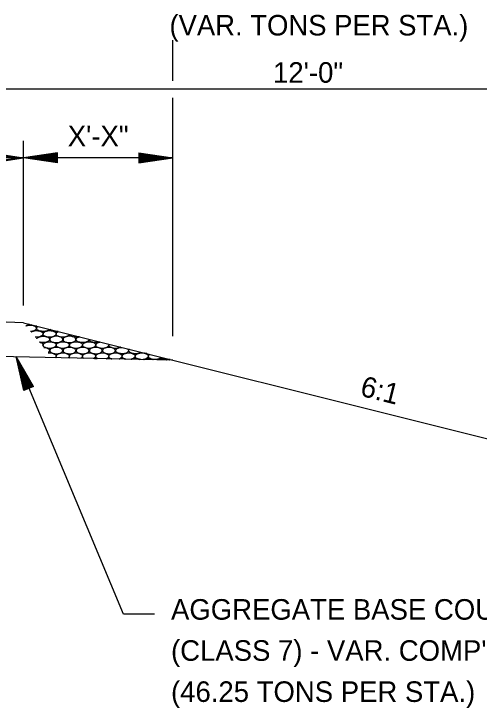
# Model space of a CAD drawing. Extents: x 138 to 3619, y -519 to 1449.
# Drawn here: x 755.2 to 890.9, y -441.4 to -238.8 of the extents above; entities that cross this region are included whole.
import ezdxf

# ---------------------------------------------------------------- set-up
doc = ezdxf.new("R2010")
doc.units = 0
doc.layers.add('R_Annotation', color=7, linetype='Continuous')
doc.layers.add('R_Dimension', color=7, linetype='Continuous')

msp = doc.modelspace()

# ---------------------------------------------------------------- linework, layer by layer
at = {"layer": 'R_Annotation'}
for p, q in [((758, -328.91), (718, -327.31)), ((758, -328.91), (958, -378.91)), ((801.63, -339.82), (688, -337.55))]:
    msp.add_line(p, q, dxfattribs=at)
at = {"layer": 'R_Dimension'}
for p, q in [((801.63, -258.28), (801.63, -246.46)), ((958, -260.78), (718, -260.78)), ((801.63, -332.86), (801.63, -263.28)), ((758, -323.91), (758, -275.78)), ((801.63, -332.86), (801.63, -275.78)), ((748, -279.28), (758, -280.78)), ((748, -279.53), (756.33, -280.78)), ((768, -279.28), (758, -280.78)), ((768, -279.53), (759.67, -280.78)), ((768, -282.28), (768, -279.28)), ((791.63, -279.28), (801.63, -280.78)), ((791.63, -279.28), (791.63, -282.28)), ((791.63, -279.53), (799.96, -280.78)), ((801.63, -280.78), (414.37, -280.78)), ((748, -282.28), (758, -280.78)), ((748, -282.03), (756.33, -280.78)), ((768, -282.28), (758, -280.78)), ((768, -282.03), (759.67, -280.78)), ((768, -279.79), (761.39, -280.78)), ((768, -281.78), (761.39, -280.78)), ((768, -280.04), (763.06, -280.78)), ((768, -281.53), (763.06, -280.78)), ((768, -280.29), (764.75, -280.78)), ((768, -281.27), (764.75, -280.78)), ((768, -280.55), (766.42, -280.78)), ((768, -281.02), (766.42, -280.78)), ((791.63, -279.79), (798.24, -280.78)), ((791.63, -280.04), (796.58, -280.78)), ((791.63, -280.3), (794.88, -280.78)), ((791.63, -280.55), (793.21, -280.78)), ((791.63, -282.28), (801.63, -280.78)), ((791.63, -281.27), (794.88, -280.78)), ((791.63, -281.78), (798.24, -280.78)), ((791.63, -282.03), (799.96, -280.78)), ((791.63, -281.53), (796.58, -280.78)), ((791.63, -281.02), (793.21, -280.78)), ((760.93, -347.56), (755.86, -338.81)), ((758.14, -348.66), (755.86, -338.81)), ((760.69, -347.65), (756.47, -340.36)), ((758.37, -348.57), (756.47, -340.36)), ((758.61, -348.48), (757.1, -341.96)), ((760.46, -347.75), (757.1, -341.96)), ((760.22, -347.84), (757.71, -343.51)), ((758.84, -348.39), (757.71, -343.51)), ((759.08, -348.29), (758.34, -345.09)), ((759.98, -347.93), (758.34, -345.09)), ((760.93, -347.56), (758.14, -348.66)), ((759.31, -348.2), (758.95, -346.64)), ((759.75, -348.03), (758.95, -346.64))]:
    msp.add_line(p, q, dxfattribs=at)
msp.add_lwpolyline([(796.21, -413.96), (787.22, -413.96), (755.91, -338.91)], dxfattribs=at)
for points in [[(759.65, -329.33), (759.64, -329.34), (759.56, -329.43), (759.33, -329.59), (759.03, -329.72), (758.8, -329.79), (758.74, -329.81)], [(758.74, -329.81), (758.75, -329.8), (758.91, -329.75), (759.16, -329.67), (759.54, -329.59), (759.78, -329.58), (759.92, -329.59)], [(759.92, -329.59), (760.14, -329.59), (760.65, -329.65), (761.1, -329.8), (761.51, -330.02), (761.63, -330.14), (761.78, -330.38), (761.81, -330.6), (761.7, -330.81), (761.52, -331.02), (761.29, -331.16), (760.85, -331.35), (760.42, -331.46), (760.16, -331.47), (760.11, -331.47)], [(761.84, -329.89), (761.82, -329.89), (761.63, -329.89), (761.27, -329.86), (760.79, -329.72), (760.48, -329.62), (760.28, -329.53), (760.22, -329.5), (760.16, -329.45)], [(761.91, -329.89), (761.89, -329.89), (761.86, -329.89), (761.84, -329.89)], [(765.53, -330.8), (765.5, -330.85), (765.4, -330.99), (765.13, -331.16), (764.69, -331.35), (764.2, -331.47), (763.7, -331.46), (763.25, -331.42), (762.9, -331.37), (762.58, -331.29), (762.28, -331.12), (762.05, -330.95), (761.89, -330.71), (761.87, -330.5), (761.92, -330.29), (762.08, -330.08), (762.15, -330.02), (762.24, -329.97)], [(760.25, -331.64), (760.29, -331.6), (760.44, -331.53), (760.73, -331.4), (761.08, -331.29), (761.46, -331.21), (761.7, -331.2), (761.84, -331.21)], [(761.84, -331.21), (761.86, -331.21), (761.87, -331.21), (761.89, -331.21)], [(763.67, -332.17), (763.67, -332.18), (763.67, -332.35), (763.57, -332.5), (763.39, -332.69), (763.17, -332.84), (762.72, -333.03), (762.35, -333.13), (762.03, -333.15), (761.94, -333.15), (761.84, -333.14)], [(761.89, -331.21), (762.11, -331.21), (762.61, -331.27), (763.06, -331.42), (763.48, -331.64), (763.61, -331.76), (763.74, -332), (763.75, -332.08), (763.76, -332.16), (763.76, -332.16), (763.76, -332.17)], [(765.68, -333.14), (765.66, -333.14), (765.47, -333.15), (765.11, -333.12), (764.63, -332.98), (764.32, -332.87), (764.02, -332.75), (763.89, -332.63), (763.76, -332.39), (763.75, -332.29), (763.75, -332.18), (763.75, -332.17)], [(763.81, -332.17), (763.81, -332.16), (763.81, -332.03), (763.84, -331.91), (764.01, -331.68), (764.21, -331.56), (764.57, -331.4), (764.92, -331.29), (765.3, -331.21), (765.54, -331.2), (765.68, -331.21)], [(765.68, -331.21), (765.7, -331.21), (765.71, -331.21), (765.73, -331.21)], [(767.51, -332.17), (767.51, -332.18), (767.51, -332.35), (767.41, -332.5), (767.23, -332.69), (767.01, -332.84), (766.56, -333.03), (766.19, -333.13), (765.87, -333.15), (765.78, -333.15), (765.68, -333.14)], [(765.73, -331.21), (765.95, -331.21), (766.45, -331.27), (766.9, -331.42), (767.32, -331.64), (767.45, -331.76), (767.58, -332), (767.59, -332.08), (767.6, -332.16), (767.6, -332.16), (767.6, -332.17)], [(768.12, -331.44), (768.06, -331.45), (767.88, -331.47), (767.54, -331.46), (767.09, -331.42), (766.74, -331.37), (766.42, -331.29), (766.15, -331.14), (765.94, -330.98), (765.85, -330.88)], [(769.52, -333.14), (769.5, -333.14), (769.31, -333.15), (768.95, -333.12), (768.47, -332.98), (768.16, -332.87), (767.86, -332.75), (767.73, -332.63), (767.6, -332.39), (767.59, -332.29), (767.59, -332.18), (767.59, -332.17)], [(767.65, -332.17), (767.65, -332.16), (767.65, -332.03), (767.68, -331.91), (767.85, -331.68), (768.01, -331.58), (768.18, -331.5), (768.23, -331.47)], [(771.35, -332.25), (771.33, -332.39), (771.18, -332.62), (770.85, -332.84), (770.4, -333.03), (770.03, -333.13), (769.71, -333.15), (769.62, -333.15), (769.52, -333.14)], [(761.84, -333.14), (761.82, -333.14), (761.7, -333.14), (761.58, -333.14), (761.48, -333.13)], [(761.91, -333.64), (761.92, -333.57), (762.04, -333.35), (762.29, -333.19), (762.65, -333.03), (763, -332.93), (763.38, -332.84), (763.62, -332.83), (763.76, -332.84)], [(763.76, -332.84), (763.98, -332.84), (764.49, -332.91), (764.94, -333.05), (765.35, -333.28), (765.47, -333.4), (765.62, -333.63), (765.65, -333.86), (765.54, -334.07), (765.36, -334.27), (765.13, -334.42), (764.69, -334.61), (764.2, -334.72), (763.7, -334.72), (763.25, -334.68), (762.9, -334.62), (762.71, -334.58), (762.69, -334.57), (762.67, -334.57)], [(767.6, -332.84), (767.82, -332.84), (768.33, -332.91), (768.78, -333.05), (769.19, -333.28), (769.31, -333.4), (769.46, -333.63), (769.49, -333.86), (769.38, -334.07), (769.2, -334.27), (768.97, -334.42), (768.53, -334.61), (768.04, -334.72), (767.54, -334.72), (767.09, -334.68), (766.74, -334.62), (766.42, -334.55), (766.12, -334.38), (765.89, -334.2), (765.73, -333.96), (765.71, -333.75), (765.76, -333.54), (765.93, -333.31), (766.13, -333.19), (766.49, -333.03), (766.84, -332.93), (767.22, -332.84), (767.46, -332.83), (767.6, -332.84)], [(771.44, -332.84), (771.66, -332.84), (772.17, -332.91), (772.62, -333.05), (773.03, -333.28), (773.15, -333.4), (773.3, -333.63), (773.33, -333.86), (773.22, -334.07), (773.04, -334.27), (772.81, -334.42), (772.37, -334.61), (771.88, -334.72), (771.38, -334.72), (770.93, -334.68), (770.58, -334.62), (770.26, -334.55), (769.96, -334.38), (769.73, -334.2), (769.57, -333.96), (769.55, -333.75), (769.6, -333.54), (769.77, -333.31), (769.97, -333.19), (770.33, -333.03), (770.68, -332.93), (771.06, -332.84), (771.3, -332.83), (771.44, -332.84)], [(773.36, -333.14), (773.34, -333.14), (773.15, -333.15), (772.79, -333.12), (772.31, -332.98), (772, -332.87), (771.7, -332.75), (771.57, -332.63), (771.45, -332.4), (771.43, -332.34), (771.43, -332.27)], [(774.33, -333), (774.32, -333), (774.09, -333.07), (773.77, -333.15), (773.46, -333.15), (773.36, -333.14)], [(777.15, -333.7), (777.16, -333.73), (777.14, -333.9), (777.06, -334.07), (776.88, -334.27), (776.65, -334.42), (776.21, -334.61), (775.72, -334.72), (775.22, -334.72), (774.77, -334.68), (774.42, -334.62), (774.1, -334.55), (773.8, -334.38), (773.57, -334.2), (773.41, -333.96), (773.39, -333.75), (773.44, -333.54), (773.61, -333.31), (773.81, -333.19), (774.08, -333.07), (774.25, -333.01), (774.32, -332.99)], [(780.33, -334.49), (780.25, -334.53), (779.96, -334.63), (779.56, -334.72), (779.06, -334.72), (778.61, -334.68), (778.26, -334.62), (777.94, -334.55), (777.64, -334.38), (777.41, -334.2), (777.25, -333.96), (777.24, -333.85), (777.25, -333.75), (777.25, -333.73)], [(762.67, -334.57), (762.89, -334.62), (763.1, -334.7), (763.48, -334.9), (763.61, -335.01), (763.74, -335.26), (763.75, -335.33), (763.76, -335.41), (763.76, -335.42), (763.76, -335.42)], [(763.67, -335.42), (763.67, -335.44), (763.67, -335.53), (763.64, -335.62), (763.6, -335.69)], [(765.68, -336.4), (765.66, -336.4), (765.47, -336.4), (765.11, -336.37), (764.63, -336.23), (764.32, -336.13), (764.02, -336), (763.89, -335.89), (763.76, -335.64), (763.75, -335.54), (763.75, -335.44), (763.75, -335.42)], [(763.81, -335.42), (763.81, -335.42), (763.81, -335.29), (763.84, -335.16), (764.01, -334.93), (764.21, -334.81), (764.57, -334.65), (764.92, -334.55), (765.3, -334.46), (765.54, -334.45), (765.68, -334.46)], [(763.94, -336.1), (764.1, -336.11), (764.54, -336.18), (764.94, -336.31), (765.35, -336.53), (765.47, -336.65), (765.62, -336.89), (765.65, -337.11), (765.54, -337.32), (765.36, -337.53), (765.29, -337.58), (765.2, -337.63), (765.2, -337.63)], [(765.68, -334.46), (765.7, -334.46), (765.71, -334.46), (765.73, -334.46)], [(767.51, -335.42), (767.51, -335.44), (767.51, -335.61), (767.41, -335.75), (767.23, -335.95), (767.01, -336.1), (766.56, -336.28), (766.19, -336.39), (765.87, -336.4), (765.78, -336.4), (765.68, -336.4)], [(767.6, -336.1), (767.82, -336.1), (768.33, -336.16), (768.78, -336.31), (769.19, -336.53), (769.31, -336.65), (769.46, -336.89), (769.49, -337.11), (769.38, -337.32), (769.2, -337.53), (768.97, -337.67), (768.53, -337.86), (768.04, -337.98), (767.54, -337.97), (767.09, -337.93), (766.74, -337.88), (766.42, -337.8), (766.12, -337.63), (765.89, -337.46), (765.73, -337.22), (765.71, -337.01), (765.76, -336.8), (765.93, -336.57), (766.13, -336.45), (766.49, -336.29), (766.84, -336.18), (767.22, -336.1), (767.46, -336.09), (767.6, -336.1)], [(765.73, -334.46), (765.95, -334.46), (766.45, -334.53), (766.9, -334.67), (767.32, -334.9), (767.45, -335.01), (767.58, -335.26), (767.59, -335.33), (767.6, -335.41), (767.6, -335.42), (767.6, -335.42)], [(769.52, -336.4), (769.5, -336.4), (769.31, -336.4), (768.95, -336.37), (768.47, -336.23), (768.16, -336.13), (767.86, -336), (767.73, -335.89), (767.6, -335.64), (767.59, -335.54), (767.59, -335.44), (767.59, -335.42)], [(767.65, -335.42), (767.65, -335.42), (767.65, -335.29), (767.68, -335.16), (767.85, -334.93), (768.05, -334.81), (768.41, -334.65), (768.76, -334.55), (769.14, -334.46), (769.38, -334.45), (769.52, -334.46)], [(769.52, -334.46), (769.54, -334.46), (769.55, -334.46), (769.57, -334.46)], [(771.35, -335.42), (771.35, -335.44), (771.35, -335.61), (771.25, -335.75), (771.07, -335.95), (770.85, -336.1), (770.4, -336.28), (770.03, -336.39), (769.71, -336.4), (769.62, -336.4), (769.52, -336.4)], [(771.44, -336.1), (771.66, -336.1), (772.17, -336.16), (772.62, -336.31), (773.03, -336.53), (773.15, -336.65), (773.3, -336.89), (773.33, -337.11), (773.22, -337.32), (773.04, -337.53), (772.81, -337.67), (772.37, -337.86), (771.88, -337.98), (771.38, -337.97), (770.93, -337.93), (770.58, -337.88), (770.26, -337.8), (769.96, -337.63), (769.73, -337.46), (769.57, -337.22), (769.55, -337.01), (769.6, -336.8), (769.77, -336.57), (769.97, -336.45), (770.33, -336.29), (770.68, -336.18), (771.06, -336.1), (771.3, -336.09), (771.44, -336.1)], [(769.57, -334.46), (769.79, -334.46), (770.29, -334.53), (770.74, -334.67), (771.16, -334.9), (771.29, -335.01), (771.42, -335.26), (771.43, -335.33), (771.44, -335.41), (771.44, -335.42), (771.44, -335.42)], [(773.36, -336.4), (773.34, -336.4), (773.15, -336.4), (772.79, -336.37), (772.31, -336.23), (772, -336.13), (771.7, -336), (771.57, -335.89), (771.44, -335.64), (771.43, -335.54), (771.43, -335.44), (771.43, -335.42)], [(771.49, -335.42), (771.49, -335.42), (771.49, -335.29), (771.52, -335.16), (771.69, -334.93), (771.89, -334.81), (772.25, -334.65), (772.6, -334.55), (772.98, -334.46), (773.22, -334.45), (773.36, -334.46)], [(773.36, -334.46), (773.38, -334.46), (773.39, -334.46), (773.41, -334.46)], [(775.19, -335.42), (775.19, -335.44), (775.19, -335.61), (775.09, -335.75), (774.91, -335.95), (774.69, -336.1), (774.24, -336.28), (773.87, -336.39), (773.55, -336.4), (773.46, -336.4), (773.36, -336.4)], [(775.28, -336.1), (775.5, -336.1), (776.01, -336.16), (776.46, -336.31), (776.87, -336.53), (776.99, -336.65), (777.14, -336.89), (777.17, -337.11), (777.06, -337.32), (776.88, -337.53), (776.65, -337.67), (776.21, -337.86), (775.72, -337.98), (775.22, -337.97), (774.77, -337.93), (774.42, -337.88), (774.1, -337.8), (773.8, -337.63), (773.57, -337.46), (773.41, -337.22), (773.39, -337.01), (773.44, -336.8), (773.61, -336.57), (773.81, -336.45), (774.17, -336.29), (774.52, -336.18), (774.9, -336.1), (775.14, -336.09), (775.28, -336.1)], [(773.41, -334.46), (773.63, -334.46), (774.13, -334.53), (774.58, -334.67), (775, -334.9), (775.13, -335.01), (775.26, -335.26), (775.27, -335.33), (775.28, -335.41), (775.28, -335.42), (775.28, -335.42)], [(777.2, -336.4), (777.18, -336.4), (776.99, -336.4), (776.63, -336.37), (776.15, -336.23), (775.84, -336.13), (775.54, -336), (775.41, -335.89), (775.28, -335.64), (775.27, -335.54), (775.27, -335.44), (775.27, -335.42)], [(775.33, -335.42), (775.33, -335.42), (775.33, -335.29), (775.36, -335.16), (775.53, -334.93), (775.73, -334.81), (776.09, -334.65), (776.44, -334.55), (776.82, -334.46), (777.06, -334.45), (777.2, -334.46)], [(777.2, -334.46), (777.22, -334.46), (777.23, -334.46), (777.25, -334.46)], [(779.03, -335.42), (779.03, -335.44), (779.03, -335.61), (778.93, -335.75), (778.75, -335.95), (778.53, -336.1), (778.08, -336.28), (777.71, -336.39), (777.39, -336.4), (777.3, -336.4), (777.2, -336.4)], [(779.12, -336.1), (779.34, -336.1), (779.85, -336.16), (780.3, -336.31), (780.71, -336.53), (780.83, -336.65), (780.98, -336.89), (781.01, -337.11), (780.9, -337.32), (780.72, -337.53), (780.49, -337.67), (780.05, -337.86), (779.56, -337.98), (779.06, -337.97), (778.61, -337.93), (778.26, -337.88), (777.94, -337.8), (777.64, -337.63), (777.41, -337.46), (777.25, -337.22), (777.23, -337.01), (777.28, -336.8), (777.45, -336.57), (777.65, -336.45), (778.01, -336.29), (778.36, -336.18), (778.74, -336.1), (778.98, -336.09), (779.12, -336.1)], [(777.25, -334.46), (777.47, -334.46), (777.97, -334.53), (778.42, -334.67), (778.84, -334.9), (778.97, -335.01), (779.1, -335.26), (779.11, -335.33), (779.12, -335.41), (779.12, -335.42), (779.12, -335.42)], [(781.04, -336.4), (781.02, -336.4), (780.83, -336.4), (780.47, -336.37), (779.99, -336.23), (779.68, -336.13), (779.38, -336), (779.25, -335.89), (779.12, -335.64), (779.11, -335.54), (779.11, -335.44), (779.11, -335.42)], [(779.17, -335.42), (779.17, -335.42), (779.17, -335.29), (779.2, -335.16), (779.37, -334.93), (779.57, -334.81), (779.93, -334.65), (780.21, -334.57), (780.39, -334.52), (780.42, -334.52)], [(782.87, -335.42), (782.87, -335.44), (782.87, -335.61), (782.77, -335.75), (782.59, -335.95), (782.37, -336.1), (781.92, -336.28), (781.55, -336.39), (781.23, -336.4), (781.14, -336.4), (781.04, -336.4)], [(782.96, -336.1), (783.18, -336.1), (783.69, -336.16), (784.14, -336.31), (784.55, -336.53), (784.67, -336.65), (784.82, -336.89), (784.85, -337.11), (784.74, -337.32), (784.56, -337.53), (784.33, -337.67), (783.89, -337.86), (783.4, -337.98), (782.9, -337.97), (782.45, -337.93), (782.1, -337.88), (781.78, -337.8), (781.48, -337.63), (781.25, -337.46), (781.09, -337.22), (781.07, -337.01), (781.12, -336.8), (781.29, -336.57), (781.49, -336.45), (781.85, -336.29), (782.2, -336.18), (782.58, -336.1), (782.82, -336.09), (782.96, -336.1)], [(782.87, -335.13), (782.88, -335.15), (782.94, -335.24), (782.95, -335.33), (782.96, -335.41), (782.96, -335.42), (782.96, -335.42)], [(784.88, -336.4), (784.86, -336.4), (784.67, -336.4), (784.31, -336.37), (783.83, -336.23), (783.52, -336.13), (783.22, -336), (783.09, -335.89), (782.96, -335.64), (782.95, -335.54), (782.95, -335.44), (782.95, -335.42)], [(783.01, -335.42), (783.01, -335.42), (783.01, -335.33), (783.02, -335.25), (783.05, -335.18)], [(786.36, -336), (786.33, -336.02), (786.15, -336.13), (785.76, -336.28), (785.39, -336.39), (785.07, -336.4), (784.98, -336.4), (784.88, -336.4)], [(788.3, -336.49), (788.43, -336.57), (788.52, -336.68), (788.66, -336.89), (788.69, -337.11), (788.58, -337.32), (788.4, -337.53), (788.17, -337.67), (787.73, -337.86), (787.24, -337.98), (786.74, -337.97), (786.29, -337.93), (785.94, -337.88), (785.62, -337.8), (785.32, -337.63), (785.09, -337.46), (784.93, -337.22), (784.91, -337.01), (784.96, -336.8), (785.13, -336.57), (785.33, -336.45), (785.69, -336.29), (786.04, -336.18), (786.4, -336.1), (786.61, -336.09), (786.72, -336.09)], [(765.28, -337.73), (765.41, -337.71), (765.55, -337.71), (765.68, -337.72)], [(765.68, -337.72), (765.7, -337.72), (765.71, -337.72), (765.73, -337.72)], [(765.73, -337.72), (765.95, -337.72), (766.45, -337.78), (766.9, -337.93), (767.32, -338.15), (767.45, -338.27), (767.58, -338.51), (767.59, -338.59), (767.6, -338.67), (767.6, -338.67), (767.6, -338.68)], [(767.65, -338.68), (767.65, -338.67), (767.65, -338.54), (767.68, -338.42), (767.85, -338.19), (768.05, -338.07), (768.41, -337.91), (768.76, -337.8), (769.14, -337.72), (769.38, -337.71), (769.52, -337.72)], [(769.52, -337.72), (769.54, -337.72), (769.55, -337.72), (769.57, -337.72)], [(769.57, -337.72), (769.79, -337.72), (770.29, -337.78), (770.74, -337.93), (771.16, -338.15), (771.29, -338.27), (771.42, -338.51), (771.43, -338.59), (771.44, -338.67), (771.44, -338.67), (771.44, -338.68)], [(771.49, -338.68), (771.49, -338.67), (771.49, -338.54), (771.52, -338.42), (771.69, -338.19), (771.89, -338.07), (772.25, -337.91), (772.6, -337.8), (772.98, -337.72), (773.22, -337.71), (773.36, -337.72)], [(773.36, -337.72), (773.38, -337.72), (773.39, -337.72), (773.41, -337.72)], [(773.41, -337.72), (773.63, -337.72), (774.13, -337.78), (774.58, -337.93), (775, -338.15), (775.13, -338.27), (775.26, -338.51), (775.27, -338.59), (775.28, -338.67), (775.28, -338.67), (775.28, -338.68)], [(775.33, -338.68), (775.33, -338.67), (775.33, -338.54), (775.36, -338.42), (775.53, -338.19), (775.73, -338.07), (776.09, -337.91), (776.44, -337.8), (776.82, -337.72), (777.06, -337.71), (777.2, -337.72)], [(777.2, -337.72), (777.22, -337.72), (777.23, -337.72), (777.25, -337.72)], [(777.25, -337.72), (777.47, -337.72), (777.97, -337.78), (778.42, -337.93), (778.84, -338.15), (778.97, -338.27), (779.1, -338.51), (779.11, -338.59), (779.12, -338.67), (779.12, -338.67), (779.12, -338.68)], [(779.17, -338.68), (779.17, -338.67), (779.17, -338.54), (779.2, -338.42), (779.37, -338.19), (779.57, -338.07), (779.93, -337.91), (780.28, -337.8), (780.66, -337.72), (780.9, -337.71), (781.04, -337.72)], [(781.04, -337.72), (781.06, -337.72), (781.07, -337.72), (781.09, -337.72)], [(781.09, -337.72), (781.31, -337.72), (781.81, -337.78), (782.26, -337.93), (782.68, -338.15), (782.81, -338.27), (782.94, -338.51), (782.95, -338.59), (782.96, -338.67), (782.96, -338.67), (782.96, -338.68)], [(783.01, -338.68), (783.01, -338.67), (783.01, -338.54), (783.04, -338.42), (783.21, -338.19), (783.41, -338.07), (783.77, -337.91), (784.12, -337.8), (784.5, -337.72), (784.74, -337.71), (784.88, -337.72)], [(784.88, -337.72), (784.9, -337.72), (784.91, -337.72), (784.93, -337.72)], [(784.93, -337.72), (785.15, -337.72), (785.65, -337.78), (786.1, -337.93), (786.52, -338.15), (786.65, -338.27), (786.78, -338.51), (786.79, -338.59), (786.8, -338.67), (786.8, -338.67), (786.8, -338.68)], [(786.85, -338.68), (786.85, -338.67), (786.85, -338.54), (786.88, -338.42), (787.05, -338.19), (787.25, -338.07), (787.61, -337.91), (787.96, -337.8), (788.34, -337.72), (788.58, -337.71), (788.72, -337.72)], [(788.72, -337.72), (788.74, -337.72), (788.75, -337.72), (788.77, -337.72)], [(792.27, -337.48), (792.21, -337.54), (792, -337.68), (791.57, -337.86), (791.08, -337.98), (790.58, -337.97), (790.13, -337.93), (789.78, -337.88), (789.46, -337.8), (789.16, -337.63), (788.93, -337.46), (788.77, -337.22), (788.75, -337.01), (788.8, -336.8), (788.9, -336.67), (788.91, -336.66), (788.92, -336.64)], [(788.77, -337.72), (788.99, -337.72), (789.49, -337.78), (789.94, -337.93), (790.36, -338.15), (790.49, -338.27), (790.62, -338.51), (790.63, -338.59), (790.64, -338.67), (790.64, -338.67), (790.64, -338.68)], [(790.69, -338.68), (790.69, -338.67), (790.69, -338.54), (790.72, -338.42), (790.89, -338.19), (791.09, -338.07), (791.45, -337.91), (791.8, -337.8), (792.18, -337.72), (792.42, -337.71), (792.56, -337.72)], [(792.56, -337.72), (792.58, -337.72), (792.59, -337.72), (792.61, -337.72)], [(792.61, -337.72), (792.83, -337.72), (793.33, -337.78), (793.78, -337.93), (794.2, -338.15), (794.33, -338.27), (794.46, -338.51), (794.47, -338.59), (794.48, -338.67), (794.48, -338.67), (794.48, -338.68)], [(794.12, -337.94), (794.07, -337.94), (793.85, -337.92), (793.62, -337.88), (793.33, -337.81), (793.23, -337.76), (793.12, -337.69)], [(794.53, -338.68), (794.53, -338.67), (794.53, -338.54), (794.56, -338.42), (794.7, -338.23), (794.77, -338.17), (794.84, -338.12)], [(767.51, -338.68), (767.51, -338.69), (767.51, -338.86), (767.41, -339.01), (767.3, -339.13), (767.3, -339.13), (767.29, -339.13)], [(767.76, -339.14), (767.72, -339.1), (767.61, -338.96), (767.59, -338.8), (767.59, -338.69), (767.59, -338.68)], [(771.35, -338.68), (771.35, -338.69), (771.35, -338.86), (771.25, -339.01), (771.11, -339.16), (771.09, -339.19), (771.06, -339.21)], [(771.69, -339.22), (771.61, -339.16), (771.46, -339), (771.43, -338.8), (771.43, -338.69), (771.43, -338.68)], [(775.19, -338.68), (775.19, -338.69), (775.19, -338.86), (775.09, -339.01), (774.92, -339.19), (774.86, -339.24), (774.8, -339.28)], [(775.65, -339.3), (775.52, -339.23), (775.4, -339.12), (775.28, -338.9), (775.27, -338.8), (775.27, -338.69), (775.27, -338.68)], [(779.03, -338.68), (779.03, -338.69), (779.03, -338.86), (778.93, -339.01), (778.75, -339.2), (778.65, -339.28), (778.53, -339.34), (778.5, -339.36)], [(778.73, -339.36), (778.86, -339.35), (778.99, -339.34), (779.12, -339.35)], [(779.69, -339.38), (779.64, -339.36), (779.42, -339.29), (779.25, -339.14), (779.12, -338.9), (779.11, -338.8), (779.11, -338.69), (779.11, -338.68)], [(779.12, -339.35), (779.25, -339.35), (779.37, -339.36), (779.5, -339.38)], [(782.87, -338.68), (782.87, -338.69), (782.87, -338.86), (782.77, -339.01), (782.59, -339.2), (782.44, -339.31), (782.28, -339.4), (782.19, -339.43)], [(782.24, -339.43), (782.24, -339.43), (782.34, -339.41), (782.58, -339.35), (782.82, -339.34), (782.96, -339.35)], [(783.78, -339.46), (783.64, -339.42), (783.33, -339.35), (783.09, -339.14), (782.96, -338.9), (782.95, -338.8), (782.95, -338.69), (782.95, -338.68)], [(782.96, -339.35), (783.18, -339.35), (783.46, -339.39), (783.73, -339.45), (783.78, -339.46)], [(785.83, -339.51), (785.91, -339.48), (786.1, -339.42), (786.42, -339.35), (786.66, -339.34), (786.8, -339.35)], [(786.71, -338.68), (786.71, -338.69), (786.71, -338.86), (786.61, -339.01), (786.43, -339.2), (786.22, -339.35), (786, -339.46), (785.85, -339.51)], [(787.9, -339.55), (787.82, -339.52), (787.59, -339.46), (787.36, -339.38), (787.06, -339.26), (786.93, -339.14), (786.8, -338.9), (786.79, -338.8), (786.79, -338.69), (786.79, -338.68)], [(786.8, -339.35), (787.02, -339.35), (787.4, -339.4), (787.75, -339.5), (787.89, -339.55)], [(790.55, -338.68), (790.55, -338.69), (790.55, -338.86), (790.45, -339.01), (790.27, -339.2), (790.05, -339.35), (789.75, -339.49), (789.52, -339.56), (789.45, -339.58)], [(789.45, -339.58), (789.46, -339.57), (789.62, -339.52), (789.88, -339.44), (790.26, -339.35), (790.5, -339.34), (790.64, -339.35)], [(792.16, -339.63), (792.11, -339.63), (791.88, -339.59), (791.51, -339.49), (791.2, -339.38), (790.9, -339.26), (790.77, -339.14), (790.64, -338.9), (790.63, -338.8), (790.63, -338.69), (790.63, -338.68)], [(790.64, -339.35), (790.86, -339.35), (791.31, -339.41), (791.72, -339.53), (791.92, -339.63)], [(794.39, -338.68), (794.39, -338.69), (794.39, -338.86), (794.29, -339.01), (794.11, -339.2), (793.89, -339.35), (793.47, -339.53), (793.12, -339.63), (792.93, -339.65)], [(793.12, -339.65), (793.19, -339.62), (793.4, -339.53), (793.72, -339.44), (794.1, -339.35), (794.34, -339.34), (794.48, -339.35)], [(796.4, -339.65), (796.38, -339.65), (796.19, -339.66), (795.83, -339.63), (795.35, -339.49), (795.04, -339.38), (794.74, -339.26), (794.61, -339.14), (794.48, -338.9), (794.47, -338.8), (794.47, -338.69), (794.47, -338.68)], [(794.48, -339.35), (794.7, -339.35), (795.21, -339.42), (795.66, -339.56), (795.91, -339.7), (795.92, -339.7), (795.92, -339.71)], [(798.16, -338.95), (798.12, -339.01), (798, -339.16), (797.73, -339.35), (797.28, -339.54), (796.91, -339.64), (796.59, -339.66), (796.5, -339.66), (796.4, -339.65)], [(796.82, -339.73), (796.83, -339.72), (796.95, -339.66), (797.21, -339.54), (797.56, -339.44), (797.94, -339.35), (798.18, -339.34), (798.32, -339.35)], [(798.32, -339.35), (798.54, -339.35), (799.05, -339.42), (799.5, -339.56), (799.79, -339.72), (799.84, -339.75), (799.88, -339.79)], [(800.24, -339.65), (800.22, -339.65), (800.03, -339.66), (799.67, -339.63), (799.19, -339.49), (798.88, -339.38), (798.59, -339.26), (798.47, -339.15), (798.38, -339.01)], [(800.81, -339.62), (800.72, -339.64), (800.53, -339.66), (800.34, -339.66), (800.24, -339.65)], [(800.54, -339.8), (800.59, -339.76), (800.7, -339.7), (800.8, -339.65), (800.85, -339.63)]]:
    msp.add_open_spline(points, degree=3, dxfattribs=at)

# ---------------------------------------------------------------- texts
at = {"layer": 'R_Annotation'}
for s, height, p in [('(VAR. TONS PER STA.)', 5.985, (800.62, -245.08)), ('12\'-0"', 6, (830.83, -258.87)), ('X\'-X"', 6, (770.94, -277.43)), ('AGGREGATE BASE COURSE', 6, (801.07, -415.57)), ("(CLASS 7) - VAR. COMP'D. DEPTH", 6, (801.07, -427.57)), ('(46.25 TONS PER STA.)', 6, (801.07, -439.57))]:
    msp.add_text(s, height=height, dxfattribs=at).set_placement(p)
msp.add_text('6:1', height=6, rotation=345.964, dxfattribs=at).set_placement((855.95, -350.15))

doc.saveas('drawing.dxf')
